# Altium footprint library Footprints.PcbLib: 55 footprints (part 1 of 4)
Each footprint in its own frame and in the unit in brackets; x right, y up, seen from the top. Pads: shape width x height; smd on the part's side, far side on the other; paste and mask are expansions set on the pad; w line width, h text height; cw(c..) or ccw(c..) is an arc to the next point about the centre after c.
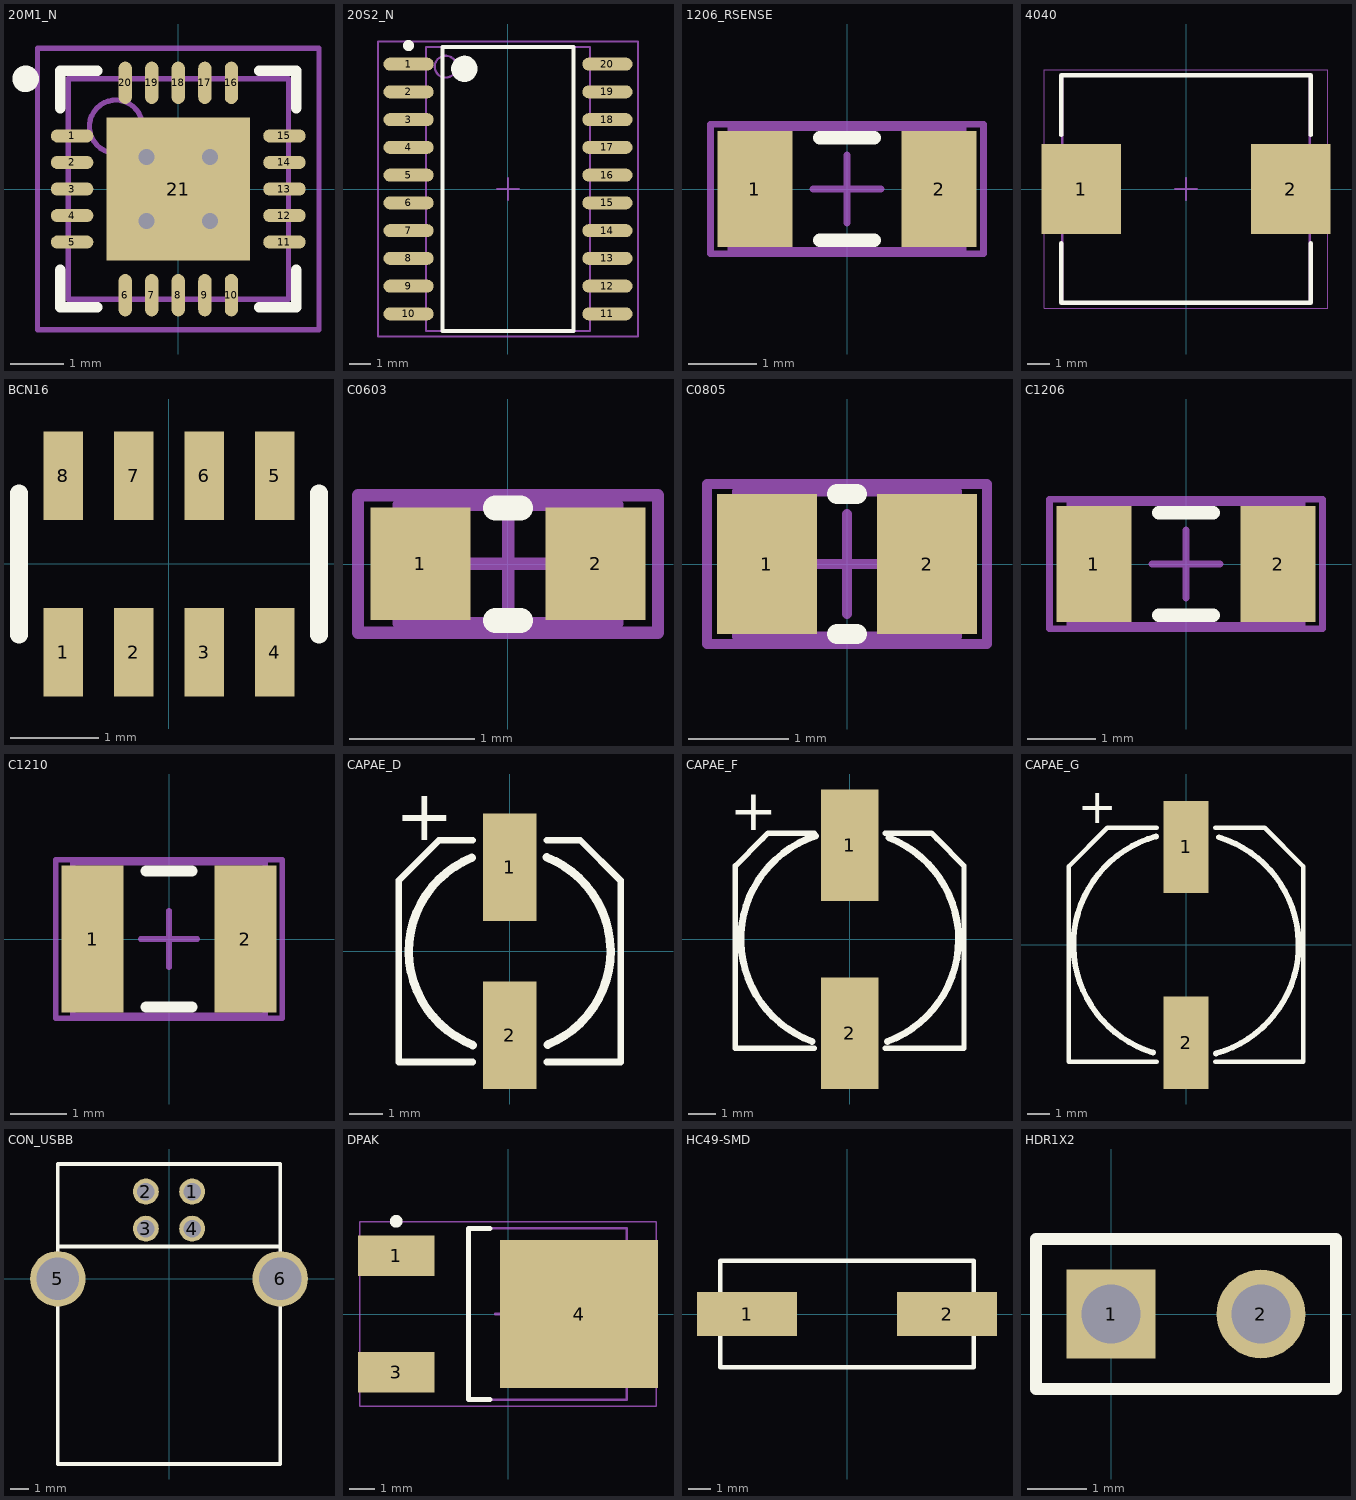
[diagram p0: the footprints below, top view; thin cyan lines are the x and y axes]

## 20M1_N [mm] "QFN, 20-Leads, Body 4x4mm, Pitch 0.5mm, IPC Medium Density"
height 0.8
pads (21):
  oval 0.8x0.25 smd: 1(-2,1) 2(-2,0.5) 3(-2,0) 4(-2,-0.5) 5(-2,-1) 11(2,-1) 12(2,-0.5) 13(2,0) 14(2,0.5) 15(2,1)
  oval 0.25x0.8 smd: 6(-1,-2) 7(-0.5,-2) 8(0,-2) 9(0.5,-2) 10(1,-2) 16(1,2) 17(0.5,2) 18(0,2) 19(-0.5,2) 20(-1,2)
  rect 2.7x2.7 smd mask+0: 21(0,0)
via 0.6,-0.6 diameter 0.7 hole 0.3
via -0.6,-0.6 diameter 0.7 hole 0.3
via 0.6,0.6 diameter 0.7 hole 0.3
via -0.6,0.6 diameter 0.7 hole 0.3
Top Overlay:
  circle w0.25: c-2.875,2.075 r0.125
  lines w0.2: -2.225,-1.525 -2.225,-2.225 -1.525,-2.225 ; -2.225,1.525 -2.225,2.225 -1.525,2.225 ; 1.525,-2.225 2.225,-2.225 2.225,-1.525 ; 1.525,2.225 2.225,2.225 2.225,1.525
Mechanical 13:
  circle w0.1: c-1.175,1.175 r0.5
  lines w0.1: -2.075,-2.075 2.075,-2.075 2.075,2.075 -2.075,2.075 -2.075,-2.075
Mechanical 15:
  lines w0.1: -0.5,0 0.5,0 ; 0,-0.5 0,0.5 ; -2.65,-2.65 2.65,-2.65 2.65,2.65 -2.65,2.65 -2.65,-2.65
3D body: height 0.78, standoff -0.02, extent -2.01,-2.01 2.01,2.01

## 20S2_N [mm] "SOIC, 20-Leads, Body 12.8x7.5mm, Pitch 1.27mm, IPC Medium Density"
height 2.65
pads (20):
  oval 2.3x0.6 smd: 1(-4.55,5.715) 2(-4.55,4.445) 3(-4.55,3.175) 4(-4.55,1.905) 5(-4.55,0.635) 6(-4.55,-0.635) 7(-4.55,-1.905) 8(-4.55,-3.175) 9(-4.55,-4.445) 10(-4.55,-5.715) 11(4.55,-5.715) 12(4.55,-4.445) 13(4.55,-3.175) 14(4.55,-1.905) 15(4.55,-0.635) 16(4.55,0.635) 17(4.55,1.905) 18(4.55,3.175) 19(4.55,4.445) 20(4.55,5.715)
Top Overlay:
  circle w0.25: c-4.55,6.565 r0.125
  circle w0.6: c-2,5.5 r0.3
  lines w0.2: -3,-6.5 -3,6.5 3,6.5 3,-6.5 -3,-6.5
Mechanical 13:
  circle w0.1: c-2.85,5.6 r0.5
  lines w0.1: -3.75,-6.5 -3.75,6.5 3.75,6.5 3.75,-6.5 -3.75,-6.5
Mechanical 15:
  lines w0.1: -0.5,0 0.5,0 ; 0,-0.5 0,0.5 ; -5.95,-6.75 -5.95,6.75 5.95,6.75 5.95,-6.75 -5.95,-6.75
3D body: height 2.65, standoff 0, extent -3.75,-6.5 3.75,6.5

## 1206_RSENSE [mm] "Chip Capacitor, Body 3.2x1.6mm, IPC High Density"
height 1.3
pads (4):
  rect 1.1x1.7 smd: 1(-1.35,0) 2(1.35,0)
  rect 0.1x0.1 smd paste+0 mask+0: 3(-0.9,-0.8) 4(0.9,-0.8)
Top Overlay:
  lines w0.2: -0.4,-0.75 0.4,-0.75 ; -0.4,0.75 0.4,0.75
Mechanical 13:
  lines w0.1: -1.7,-0.9 1.7,-0.9 1.7,0.9 -1.7,0.9 -1.7,-0.9
Mechanical 15:
  lines w0.1: -0.5,0 0.5,0 ; 0,-0.5 0,0.5 ; -2,-0.95 2,-0.95 2,0.95 -2,0.95 -2,-0.95
3D body: height 1.3, standoff 0, extent -1.7,-0.9 1.7,0.9

## 4040 [mm] "Precision Wire Wound Inductor, 2-Leads, Body 10.92x10.30mm, IPC Medium Density"
height 4
pads (2):
  rect 3.6x4.1 smd: 1(-4.75,0) 2(4.75,0)
Top Overlay:
  lines w0.2: -5.65,-2.45 -5.65,-5.15 5.65,-5.15 5.65,-2.45 ; -5.65,2.45 -5.65,5.15 5.65,5.15 5.65,2.45
Mechanical 13:
  lines w0.1: -5.61,-5.15 -5.61,5.15 5.61,5.15 5.61,-5.15 -5.61,-5.15
Mechanical 15:
  lines w0.05: -6.425,-5.4 -6.425,5.4 6.425,5.4 6.425,-5.4 -6.425,-5.4
  lines w0.1: -0.5,0 0.5,0 ; 0,-0.5 0,0.5
3D body: height 4, standoff 0, extent -5.61,-5.15 5.61,5.15

## BCN16 [mm]
height 0.5
pads (8):
  rect 0.45x1 smd: 1(-1.2,-1) 2(-0.4,-1) 3(0.4,-1) 4(1.2,-1) 5(1.2,1) 6(0.4,1) 7(-0.4,1) 8(-1.2,1)
Top Overlay:
  lines w0.2: -1.7,-0.8 -1.7,0.8 ; 1.7,-0.8 1.7,0.8
3D body: height 0.5, standoff 0, extent -1.6,-0.8 1.6,0.8

## C0603 [mm] "Chip Capacitor, Body 1.6x0.8mm, IPC High Density"
height 1.3
pads (2):
  rect 0.8x0.9 smd: 1(-0.7,0) 2(0.7,0)
Top Overlay:
  lines w0.2: -0.1,-0.45 0.1,-0.45 ; -0.1,0.45 0.1,0.45
Mechanical 13:
  lines w0.1: -0.875,-0.475 -0.875,0.475 0.875,0.475 0.875,-0.475 -0.875,-0.475
Mechanical 15:
  lines w0.1: -0.475,0 0.475,0 ; 0,-0.475 0,0.475 ; -1.2,-0.55 -1.2,0.55 1.2,0.55 1.2,-0.55 -1.2,-0.55
3D body: height 0.55, standoff 0, extent -0.8,-0.4 0.8,0.4

## C0805 [mm] "Chip Capacitor, Body 2.0x1.3mm, IPC High Density"
height 1.4
pads (2):
  rect 1x1.4 smd: 1(-0.8,0) 2(0.8,0)
Top Overlay:
  lines w0.2: -0.1,-0.7 0.1,-0.7 ; -0.1,0.7 0.1,0.7
Mechanical 13:
  lines w0.1: -1.1,-0.725 1.1,-0.725 1.1,0.725 -1.1,0.725 -1.1,-0.725
Mechanical 15:
  lines w0.1: -0.5,0 0.5,0 ; 0,-0.5 0,0.5 ; -1.4,-0.8 1.4,-0.8 1.4,0.8 -1.4,0.8 -1.4,-0.8
3D body: height 0.88, standoff 0, extent -0.95,-0.6 1.05,0.6

## C1206 [mm] "Chip Capacitor, Body 3.2x1.6mm, IPC High Density"
height 1.3
pads (2):
  rect 1.1x1.7 smd: 1(-1.35,0) 2(1.35,0)
Top Overlay:
  lines w0.2: -0.4,-0.75 0.4,-0.75 ; -0.4,0.75 0.4,0.75
Mechanical 13:
  lines w0.1: -1.7,-0.9 -1.7,0.9 1.7,0.9 1.7,-0.9 -1.7,-0.9
Mechanical 15:
  lines w0.1: -0.5,0 0.5,0 ; 0,-0.5 0,0.5 ; -2,-0.95 -2,0.95 2,0.95 2,-0.95 -2,-0.95
3D body: height 0.94, standoff 0, extent -1.6,-0.8 1.6,0.8

## C1210 [mm] "Chip Capacitor, Body 3.2x2.5mm, IPC High Density"
height 1.3
pads (2):
  rect 1.1x2.6 smd: 1(-1.35,0) 2(1.35,0)
Top Overlay:
  lines w0.2: -0.4,-1.2 0.4,-1.2 ; -0.4,1.2 0.4,1.2
Mechanical 13:
  lines w0.1: -1.7,-1.35 1.7,-1.35 1.7,1.35 -1.7,1.35 -1.7,-1.35
Mechanical 15:
  lines w0.1: -0.5,0 0.5,0 ; 0,-0.5 0,0.5 ; -2,-1.4 2,-1.4 2,1.4 -2,1.4 -2,-1.4
3D body: height 1.55, standoff 0, extent -1.6,-1.25 1.6,1.25

## CAPAE_D [mm]
height 5.4
pads (2):
  rect 1.6x3.2 smd: 1(0,2.5) 2(0,-2.5)
Top Overlay:
  lines w0.2: -1.1,-3.3 -3.3,-3.3 -3.3,2.1 -2.1,3.3 -1.1,3.3 ; 1.1,-3.3 3.3,-3.3 3.3,2.1 2.1,3.3 1.1,3.3
  lines w0.254: -1.132,2.778 ccw(c0,0) -1.097,-2.792 ; 1.097,2.792 cw(c0,0) 1.132,-2.778
  text "+" at -3.4,3.3 h1.52
3D body: height 5.9, standoff 0.5, extent -3.1,-3.114 3.115,3.114
3D body: height 0.5, standoff 0, extent -3.3,-3.3 3.3,3.3

## CAPAE_F [mm] "8mm DIA"
height 10.5
pads (2):
  rect 2.1x4.1 smd: 1(0,3.45) 2(0,-3.45)
Top Overlay:
  lines w0.2: -1.3,-4 -4.2,-4 -4.2,2.7 -3.2,3.7 -3,3.9 -1.3,3.9 ; 1.3,-4 4.2,-4 4.2,2.7 3.2,3.7 3,3.9 1.3,3.9
  lines w0.254: -1.383,-3.753 cw(c0,0) -1.265,3.795 ; 1.383,-3.753 ccw(c0,0) 1.436,3.733
  text "+" at -4.4,4 h1.52
3D body: height 10.2, standoff 0, extent -4.175,-4.95 4.125,4.95

## CAPAE_G [mm]
height 10.2
pads (2):
  rect 2x4.1 smd: 1(0,4.35) 2(0,-4.35)
Top Overlay:
  lines w0.2: -1.3,-5.2 -5.2,-5.2 -5.2,3.5 -3.5,5.2 -1.3,5.2 ; 1.3,-5.2 5.2,-5.2 5.2,3.5 3.5,5.2 1.3,5.2
  lines w0.254: -1.464,-4.781 cw(c0,0) -1.333,4.819 ; 1.333,-4.819 ccw(c0,0) 1.464,4.781
  text "+" at -4.8,5.4 h1.52
3D body: height 10.2, standoff 0, extent -5.155,-5.8 5.145,5.8

## CON_USBB [mm]
height 10
pads (6):
  round 1.4 hole 0.95: 1(1.25,4.71) 2(-1.25,4.71) 3(-1.25,2.71) 4(1.25,2.71)
  round 3 hole 2.3: 5(-6,0) 6(6,0)
Top Overlay:
  lines w0.2: -6,1.75 6,1.75 ; -6,-10 -6,6.2 6,6.2 6,-10 -6,-10
3D body: height 11, standoff -4.42, extent -7.442,-10.2 7.442,6.8

## DPAK [mm] "D-PAK, 3-Pads, Body 6.21x6.73mm (max), IPC Medium Density"
height 2.38
pads (3):
  rect 3x1.6 smd: 1(-4.39,2.29) 3(-4.39,-2.29)
  rect 6.2x5.8 smd: 4(2.79,0)
Top Overlay:
  circle w0.25: c-4.39,3.64 r0.125
  lines w0.2: -0.71,-3.35 -1.55,-3.35 -1.55,3.35 -0.71,3.35
Mechanical 13:
  lines w0.1: -1.55,-3.375 4.67,-3.375 4.67,3.375 -1.55,3.375 -1.55,-3.375
Mechanical 15:
  lines w0.05: -5.825,-3.625 5.825,-3.625 5.825,3.625 -5.825,3.625 -5.825,-3.625
  lines w0.1: -0.5,0 0.5,0 ; 0,-0.5 0,0.5
3D body: height 2.29, standoff -0.12, extent -4.55,-3.245 5.388,3.295

## HC49-SMD [mm]
height 4.5
pads (2):
  rect 4.5x2 smd: 1(-4.5,0) 2(4.5,0)
Top Overlay:
  lines w0.2: -5.7,-2.4 5.7,-2.4 5.7,2.4 -5.7,2.4 -5.7,-2.4
3D body: height 2.52, standoff 0, extent -7.45,-2.25 7.55,2.25

## HDR1X2 [mm] "Connector; Header; 2 Position"
pads (2):
  rect 1.5x1.5 hole 1: 1(0,0)
  round 1.5 hole 1: 2(2.54,0)
Top Overlay:
  lines w0.2: -1.27,-1.27 -1.27,1.27 3.81,1.27 3.81,-1.27 -1.27,-1.27
3D body: height 8.44, standoff -2.54, extent -1.29,-1.225 3.79,1.315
